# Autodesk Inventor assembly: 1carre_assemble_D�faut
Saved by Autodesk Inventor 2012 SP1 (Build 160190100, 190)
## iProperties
Created: 2011-01
Part Number: 1carre_assemble_D�faut
Document SubType Name: Assembly
Designer: eric
Mass: 25.4449 g
Surface Area: 362.356 cm^2
Volume: 25.4449 cm^3
Density: 1 g/cm^3
Author: eric
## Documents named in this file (6)
- D:\Cours\Inventor salle SI\chariot_de_golf_2008\chariot_de_golf_trolem\1carre_assemble_Defaut.iam
- D:\Cours\Inventor salle SI\chariot_de_golf_2008\chariot_de_golf_trolem\bead40_Defaut.ipt
- D:\Cours\Inventor salle SI\chariot_de_golf_2008\chariot_de_golf_trolem\1plaque_avant_boitier_Defaut.ipt
- D:\Cours\Inventor salle SI\chariot_de_golf_2008\chariot_de_golf_trolem\1plaque_arriere_Defaut.ipt
- D:\Cours\Inventor salle SI\chariot_de_golf_2008\chariot_de_golf_trolem\bead41_Defaut.ipt
- D:\Cours\Inventor salle SI\chariot_de_golf_2008\chariot_de_golf_trolem\1carre_support_Defaut.ipt
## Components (5 placed, 5 different names)
1. bead40_Defaut:1
2. 1plaque_avant_boitier_Defaut:1
3. 1plaque_arriere_Defaut:1
4. bead41_Defaut:1
5. 1carre_support_Defaut:1
